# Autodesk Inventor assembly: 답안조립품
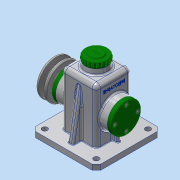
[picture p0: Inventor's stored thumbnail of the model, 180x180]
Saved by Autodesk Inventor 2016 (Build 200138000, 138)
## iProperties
Created: 2018-10
Part Number: 답안조립품
Material: 일반
Document SubType Name: Assembly
Designer: user
Author: user
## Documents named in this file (14)
- C:\Users\user\Desktop\481016V1006\답안조립품.iam
- C:\Users\user\Desktop\481016V1006\본체.ipt
- C:\Users\user\Desktop\481016V1006\뒤커버.ipt
- C:\Users\user\Desktop\481016V1006\앞커버.ipt
- C:\Users\user\Desktop\481016V1006\베어링 15 x 35 x 11.ipt
- C:\Users\user\Desktop\481016V1006\축.ipt
- C:\Users\user\Desktop\481016V1006\멈춤링 15 x 1.ipt
- C:\Users\user\Desktop\481016V1006\키 5 x 5 x 14.ipt
- C:\Users\user\Desktop\481016V1006\V-벨트풀리.ipt
- C:\Users\user\Desktop\481016V1006\오일실 15 25 7.ipt
- C:\Users\user\Desktop\481016V1006\볼트 M6 x 12.ipt
- C:\Users\user\Desktop\481016V1006\와셔.ipt
- C:\Users\user\Desktop\481016V1006\상부캡.ipt
- C:\Users\user\Desktop\481016V1006\볼트 M4 x 10.ipt
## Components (1 placed, 1 different names)
1. V-벨트풀리:1 — 각도:1
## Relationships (1: Angle 1)
- 각도:1 [Angle]: V-벨트풀리:1
